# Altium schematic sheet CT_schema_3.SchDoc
size 362 x 192 mm
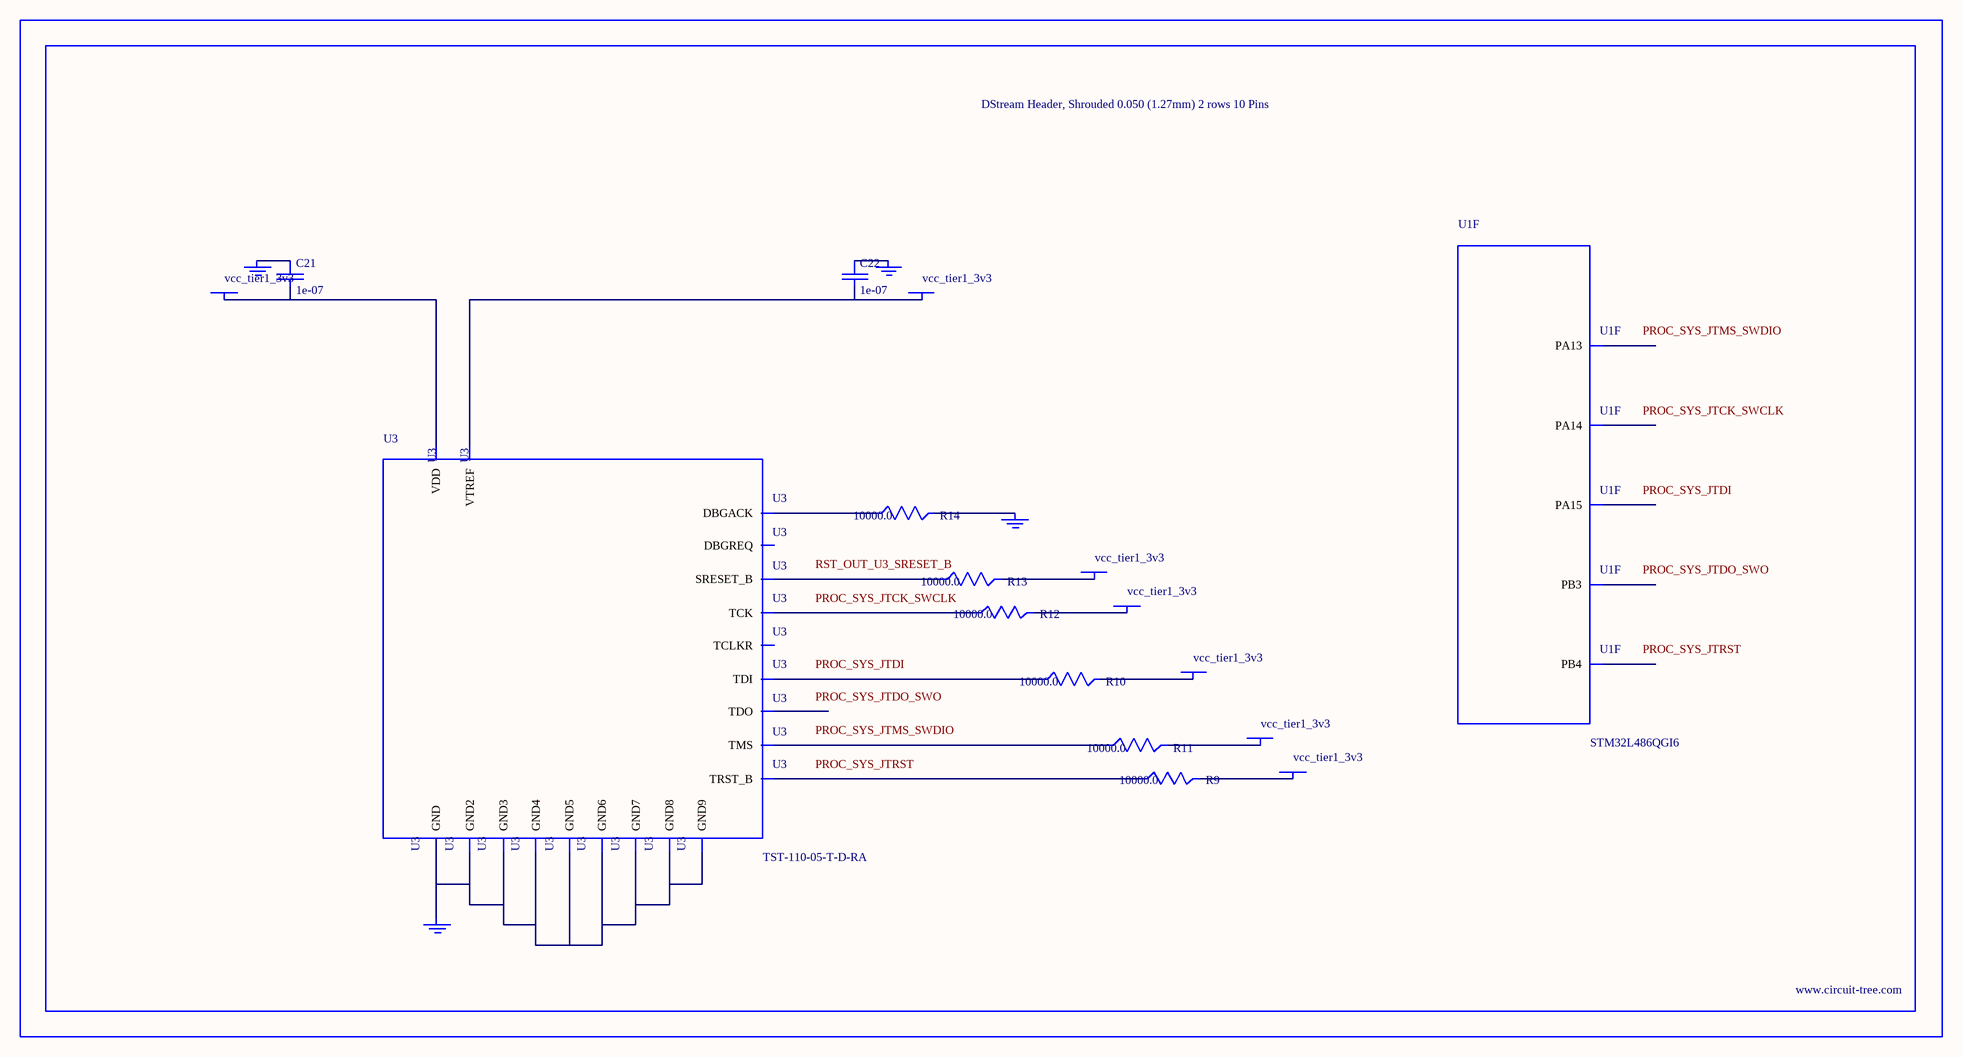
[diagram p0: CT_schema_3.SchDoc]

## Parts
BORDER2  (no value)
C21  1e-07  [C0402]
C22  1e-07  [C0402]
GND_INSTANCE_2_0  (no value)
GND_INSTANCE_2_1  (no value)
GND_INSTANCE_2_2  (no value)
GND_INSTANCE_2_3  (no value)
POWER_INSTANCE_2_0  vcc_tier1_3v3
POWER_INSTANCE_2_1  vcc_tier1_3v3
POWER_INSTANCE_2_2  vcc_tier1_3v3
POWER_INSTANCE_2_3  vcc_tier1_3v3
POWER_INSTANCE_2_4  vcc_tier1_3v3
POWER_INSTANCE_2_5  vcc_tier1_3v3
POWER_INSTANCE_2_6  vcc_tier1_3v3
R9  10000.0  [R0603]
R10  10000.0  [R0603]
R11  10000.0  [R0603]
R12  10000.0  [R0603]
R13  10000.0  [R0603]
R14  10000.0  [R0603]
U1  STM32L486QGI6  [UFBGA132]  (part F of 13)
U3  TST-110-05-T-D-RA  [TST-110-05-T-D-RA]

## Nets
NetC21_1: C21.1 GND_INSTANCE_2_1.0(GND)
NetC21_2: C21.2 POWER_INSTANCE_2_1.0(PWR) U3.2(VDD)
NetC22_1: C22.1 GND_INSTANCE_2_0.0(GND)
NetC22_2: C22.2 POWER_INSTANCE_2_0.0(PWR) U3.1(VTREF)
NetGND_INSTANCE_2_2_0: GND_INSTANCE_2_2.0(GND) R14.2
NetGND_INSTANCE_2_3_0: GND_INSTANCE_2_3.0(GND) U3.4(GND) U3.6(GND2) U3.8(GND3) U3.10(GND4) U3.12(GND5) U3.14(GND6) U3.16(GND7) U3.18(GND8) U3.20(GND9)
NetPOWER_INSTANCE_2_2_0: POWER_INSTANCE_2_2.0(PWR) R9.2
NetPOWER_INSTANCE_2_3_0: POWER_INSTANCE_2_3.0(PWR) R10.2
NetPOWER_INSTANCE_2_4_0: POWER_INSTANCE_2_4.0(PWR) R11.2
NetPOWER_INSTANCE_2_5_0: POWER_INSTANCE_2_5.0(PWR) R12.2
NetPOWER_INSTANCE_2_6_0: POWER_INSTANCE_2_6.0(PWR) R13.2
NetR9_1: R9.1 U3.3(TRST_B)
NetR10_1: R10.1 U3.5(TDI)
NetR11_1: R11.1 U3.7(TMS)
NetR12_1: R12.1 U3.9(TCK)
NetR13_1: R13.1 U3.15(SRESET_B)
NetR14_1: R14.1 U3.19(DBGACK)

Not connected (* = marked no-connect by the designer): U1 A7(PB4) A8(PB3) A9(PA15) A10(PA14) A11(PA13); U3 11(TCLKR) 13(TDO) 17(DBGREQ)

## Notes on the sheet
- Labels drawn without touching a wire or pin: PROC_SYS_JTCK_SWCLK, PROC_SYS_JTDI, PROC_SYS_JTDO_SWO, PROC_SYS_JTMS_SWDIO, PROC_SYS_JTRST, RST_OUT_U3_SRESET_B

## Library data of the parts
BORDER2 = BORDER_PAGE2
C21 C22 = C0402C104K3RACTU
GND_INSTANCE_2_0-GND_INSTANCE_2_3 = GND
POWER_INSTANCE_2_0-POWER_INSTANCE_2_6 = PWR
R9-R14 = RC0603JR-0710KL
